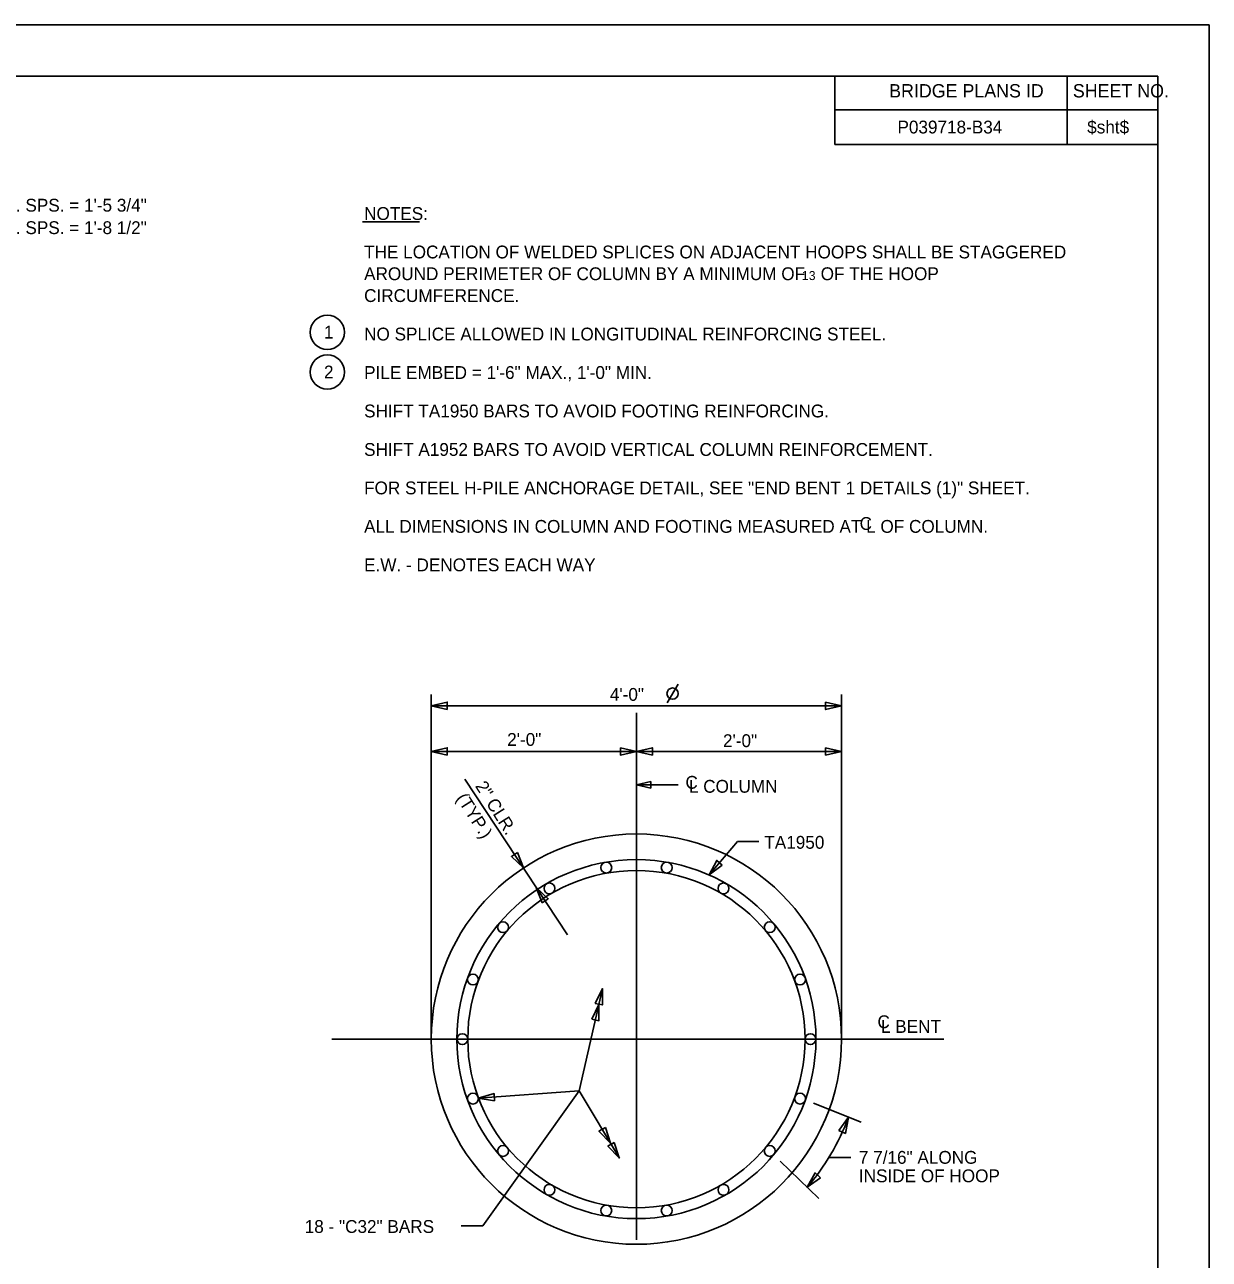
# Model space of a CAD drawing. Extents: x 1970675.2 to 1970711.3, y 796145.2 to 796167.2.
# Drawn here: x 1970699.69 to 1970711.24, y 796155.21 to 796167.25 of the extents above; entities that cross this region are included whole.
import ezdxf

# ---------------------------------------------------------------- set-up
doc = ezdxf.new("R2010")
doc.units = 0
for name, color, linetype in [('BR_AUTO DIMENSION', 7, 'Continuous'), ('BR_BORDER LINES', 7, 'Continuous'), ('BR_CENTER LINES', 7, 'Continuous'), ('BR_PRESTRESSED BEAM', 7, 'Continuous'), ('BR_REBAR', 7, 'Continuous'), ('BR_TEXT', 7, 'Continuous'), ('Level 31', 7, 'Continuous')]:
    doc.layers.add(name, color=color, linetype=linetype)

msp = doc.modelspace()

# ---------------------------------------------------------------- linework, layer by layer
at = {"layer": 'BR_AUTO DIMENSION'}
for p, q in [((1970703.651, 796157.357), (1970703.651, 796160.718)), ((1970707.651, 796159.386), (1970707.651, 796160.718)), ((1970703.651, 796160.606), (1970707.651, 796160.606)), ((1970703.651, 796160.162), (1970707.651, 796160.162)), ((1970704.98, 796158.374), (1970703.978, 796159.89)), ((1970705.651, 796159.835), (1970706.057, 796159.835)), ((1970706.36, 796158.958), (1970706.638, 796159.284)), ((1970706.638, 796159.284), (1970706.845, 796159.284)), ((1970707.651, 796157.357), (1970707.651, 796159.386)), ((1970705.32, 796157.85), (1970705.092, 796156.853)), ((1970704.109, 796156.781), (1970705.092, 796156.853)), ((1970705.092, 796156.853), (1970704.155, 796155.538)), ((1970705.485, 796156.198), (1970705.092, 796156.853)), ((1970705.485, 796156.198), (1970705.092, 796156.853)), ((1970707.377, 796156.732), (1970707.843, 796156.546)), ((1970707.051, 796156.168), (1970707.428, 796155.803)), ((1970707.741, 796156.203), (1970707.528, 796156.203)), ((1970704.155, 796155.538), (1970703.941, 796155.538))]:
    msp.add_line(p, q, dxfattribs=at)
for points in [[(1970703.807, 796160.57), (1970703.651, 796160.606), (1970703.807, 796160.642)], [(1970707.495, 796160.642), (1970707.651, 796160.606), (1970707.495, 796160.57)], [(1970703.807, 796160.126), (1970703.651, 796160.162), (1970703.807, 796160.198)], [(1970705.495, 796160.198), (1970705.651, 796160.162), (1970705.495, 796160.126)], [(1970705.807, 796160.126), (1970705.651, 796160.162), (1970705.807, 796160.198)], [(1970707.495, 796160.198), (1970707.651, 796160.162), (1970707.495, 796160.126)], [(1970705.79, 796159.803), (1970705.651, 796159.835), (1970705.79, 796159.867)], [(1970704.493, 796159.176), (1970704.549, 796159.026), (1970704.433, 796159.137)], [(1970706.488, 796159.053), (1970706.36, 796158.958), (1970706.434, 796159.1)], [(1970704.731, 796158.685), (1970704.675, 796158.835), (1970704.791, 796158.725)], [(1970705.25, 796157.706), (1970705.32, 796157.85), (1970705.32, 796157.69)], [(1970705.216, 796157.552), (1970705.286, 796157.696), (1970705.286, 796157.536)], [(1970704.267, 796156.755), (1970704.109, 796156.781), (1970704.263, 796156.827)], [(1970707.623, 796156.467), (1970707.719, 796156.595), (1970707.689, 796156.438)], [(1970705.348, 796156.496), (1970705.397, 796156.344), (1970705.286, 796156.459)], [(1970705.435, 796156.351), (1970705.484, 796156.199), (1970705.373, 796156.314)], [(1970707.446, 796156.004), (1970707.315, 796155.913), (1970707.393, 796156.053)]]:
    msp.add_lwpolyline(points, close=True, dxfattribs=at)
for centre in [(1970702.638, 796164.248), (1970702.638, 796163.86)]:
    msp.add_circle(centre, 0.167, dxfattribs=at)
msp.add_arc((1970705.651, 796157.357), 2.203, 319.0275, 339.7613, dxfattribs=at)
at = {"layer": 'BR_BORDER LINES'}
for p, q in [((1970710.736, 796166.746), (1970677.07, 796166.746)), ((1970707.584, 796166.08), (1970707.584, 796166.746)), ((1970709.85, 796166.08), (1970709.85, 796166.746)), ((1970710.736, 796145.746), (1970710.736, 796166.746)), ((1970707.584, 796166.417), (1970710.736, 796166.417)), ((1970709.85, 796166.417), (1970710.736, 796166.417)), ((1970710.736, 796166.08), (1970707.584, 796166.08))]:
    msp.add_line(p, q, dxfattribs=at)
at = {"layer": 'BR_CENTER LINES'}
for p, q in [((1970705.651, 796155.399), (1970705.651, 796160.538)), ((1970708.647, 796157.357), (1970702.682, 796157.357))]:
    msp.add_line(p, q, dxfattribs=at)
at = {"layer": 'BR_PRESTRESSED BEAM'}
msp.add_circle((1970705.651, 796157.357), 2, dxfattribs=at)
at = {"layer": 'BR_REBAR'}
for centre, radius in [((1970705.651, 796157.357), 1.75), ((1970705.357, 796159.029), 0.0529), ((1970705.946, 796159.029), 0.0529), ((1970704.803, 796158.827), 0.0529), ((1970706.5, 796158.827), 0.0529), ((1970704.351, 796158.448), 0.0529), ((1970706.951, 796158.448), 0.0529), ((1970704.057, 796157.938), 0.0529), ((1970707.246, 796157.938), 0.0529), ((1970703.954, 796157.357), 0.0529), ((1970707.348, 796157.357), 0.0529), ((1970704.057, 796156.777), 0.0529), ((1970707.246, 796156.777), 0.0529), ((1970704.351, 796156.267), 0.0529), ((1970706.951, 796156.267), 0.0529), ((1970704.803, 796155.888), 0.0529), ((1970706.5, 796155.888), 0.0529), ((1970705.357, 796155.686), 0.0529), ((1970705.946, 796155.686), 0.0529)]:
    msp.add_circle(centre, radius, dxfattribs=at)
at = {"layer": 'BR_TEXT'}
for p, q in [((1970702.981, 796165.324), (1970703.536, 796165.324)), ((1970705.952, 796160.635), (1970706.057, 796160.817)), ((1970703.651, 796160.162), (1970703.762, 796160.162)), ((1970705.651, 796160.162), (1970705.537, 796160.162)), ((1970705.651, 796160.162), (1970705.774, 796160.162)), ((1970706.964, 796160.162), (1970706.846, 796160.162))]:
    msp.add_line(p, q, dxfattribs=at)
msp.add_circle((1970706.004, 796160.726), 0.055, dxfattribs=at)
at = {"layer": 'Level 31'}
msp.add_line((1970711.236, 796167.246), (1970675.236, 796167.246), dxfattribs=at)
msp.add_lwpolyline([(1970675.236, 796167.246), (1970675.236, 796145.246), (1970711.236, 796145.246), (1970711.236, 796167.246)], dxfattribs=at)
msp.add_circle((1970705.651, 796157.357), 1.644, dxfattribs=at)

# ---------------------------------------------------------------- texts
at = {"layer": 'BR_TEXT'}
for s, height, p in [('BRIDGE PLANS ID', 0.13, (1970708.115, 796166.537)), ('SHEET NO.', 0.13, (1970709.906, 796166.537)), ('P039718-B34', 0.125, (1970708.196, 796166.186)), ('$sht$', 0.125, (1970710.046, 796166.186)), ('NOTES:', 0.125, (1970702.996, 796165.343)), ('THE LOCATION OF WELDED SPLICES ON ADJACENT HOOPS SHALL BE STAGGERED', 0.125, (1970702.996, 796164.968)), ('AROUND PERIMETER OF COLUMN BY A MINIMUM OF ', 0.125, (1970702.996, 796164.756)), ('1', 0.0875, (1970707.263, 796164.757)), ('3', 0.0875, (1970707.332, 796164.757)), (' OF THE HOOP', 0.125, (1970707.401, 796164.756)), ('CIRCUMFERENCE.', 0.125, (1970702.996, 796164.543)), ('1', 0.125, (1970702.605, 796164.187)), ('NO SPLICE ALLOWED IN LONGITUDINAL REINFORCING STEEL.', 0.125, (1970702.996, 796164.168)), ('2', 0.125, (1970702.605, 796163.798)), ('PILE EMBED = 1\'-6" MAX., 1\'-0" MIN.', 0.125, (1970702.996, 796163.793)), ('SHIFT TA1950 BARS TO AVOID FOOTING REINFORCING.', 0.125, (1970702.996, 796163.418)), ('SHIFT A1952 BARS TO AVOID VERTICAL COLUMN REINFORCEMENT.', 0.125, (1970702.996, 796163.043)), ('FOR STEEL H-PILE ANCHORAGE DETAIL, SEE "END BENT 1 DETAILS (1)" SHEET.', 0.125, (1970702.996, 796162.668)), ('ALL DIMENSIONS IN COLUMN AND FOOTING MEASURED AT L OF COLUMN. ', 0.125, (1970702.996, 796162.293)), ('C', 0.125, (1970707.827, 796162.321)), ('E.W. - DENOTES EACH WAY', 0.125, (1970702.996, 796161.918)), ('C', 0.125, (1970706.129, 796159.798)), ('C', 0.125, (1970708.001, 796157.464))]:
    msp.add_text(s, height=height, dxfattribs=at).set_placement(p)
for s, rotation, p in [('- 3 EQ. SPS. = 1\'-5 3/4"', 360, (1970699.118, 796165.424)), ('- 3 EQ. SPS. = 1\'-8 1/2"', 360, (1970699.118, 796165.205)), ('4\'-0" ', 360, (1970705.392, 796160.655)), ('2\'-0"', 360, (1970704.391, 796160.216)), ('2\'-0"', 360, (1970706.495, 796160.204)), ('2" CLR.', 302.3602, (1970704.075, 796159.824)), ('L COLUMN', 360, (1970706.163, 796159.759)), ('(TYP.)', 302.3602, (1970703.89, 796159.707)), ('TA1950', 360, (1970706.898, 796159.213)), ('L BENT', 360, (1970708.035, 796157.418)), ('7 7/16" ALONG', 360, (1970707.82, 796156.142)), ('INSIDE OF HOOP', 360, (1970707.82, 796155.962)), ('18 - "C32" BARS', 360, (1970702.417, 796155.468))]:
    msp.add_text(s, height=0.125, rotation=rotation, dxfattribs=at).set_placement(p)

doc.saveas('drawing.dxf')
